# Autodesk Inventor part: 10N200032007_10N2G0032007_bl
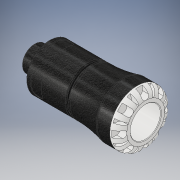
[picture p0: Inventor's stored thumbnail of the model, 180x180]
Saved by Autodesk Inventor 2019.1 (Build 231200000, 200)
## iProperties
Created: 2016-12
Part Number: 10N200032007_10N2G0032007_bl
Material: PVC-Piping
Description: PLASSON MALE ADAPTOR 32X3/4" SERIES 1
Document SubType Name: Modeling
Designer: KIM
Mass: 61.7504 g
Surface Area: 140.097 cm^2
Volume: 44.1074 cm^3
Density: 1.4 g/cm^3
Appearance: Black Cast
Author: KIM
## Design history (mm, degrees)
derived "10N20.ipt"
feature "Solid1::10N20.ipt" dims "ScaleForDerivedMember" = 10
tag "TaggingFeature1"
body "Solid1"
other parameters: "d0" = 118 [user parameter], "d1" = 23.1 [user parameter], "d2" = 32 [user parameter], "d4" = 58 [user parameter], "d6" = 55 [user parameter], "d8" = 49.3 [user parameter], "d13" = 7.2 [user parameter], "d14" = 7.2 [user parameter], "d15" = 0 [user parameter], "d17" = 360 deg [user parameter], "d19" = 8 deg [user parameter], "d20" = 0.64 [user parameter], "d21" = 0.64 [user parameter], "d22" = 8 deg [user parameter], "d24" = 0 [user parameter], "d26" = 360 deg [user parameter], "d32" = 0.925 [user parameter], "d33" = 5.8 [user parameter], "d34" = 26.441 [user parameter], "d35" = 6.4 [user parameter], "d38" = 16 [user parameter], "d39" = 0.79323 [user parameter], "d42" = 11.2 [user parameter], "d43" = 7.36 [user parameter], "d45" = 14.112 [user parameter], "d46" = 0 [user parameter], "d59" = 360 deg [user parameter], "d61" = 9.52 [user parameter], "d62" = 0.64 [user parameter], "d64" = 0 [user parameter], "d65" = 0.58 [user parameter], "d69" = 2 [user parameter], "d70" = 1.77 [user parameter], "d71" = 3 [user parameter], "d73" = 1 [user parameter], "d_" = 32 [user parameter], "E_" = 58 [user parameter], "H_" = 118 [user parameter], "l_" = 55 [user parameter], "R_" = 26.441 [user parameter], "l_2" = 16 [user parameter], "d9" = 9 [user parameter], "d11" = 58 [user parameter]
